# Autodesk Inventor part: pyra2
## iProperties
Created: 2004-12
Part Number: pyra2
Cost Center: 0.004 kg
Document SubType Name: Modeling
Designer: jwagner
Authority: 3897 mm^3
Manufacturer: Standard
Standards Organization: Custom
Author: jwagner
SaveDate: 2004-11-30
SaveTime: 11:56
TotalMass: 0.004 kg
TotalVolume: 3897 mm^3
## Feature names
1. Extrusion1
2. Trennen1
3. Trennen2
4. Trennen3
